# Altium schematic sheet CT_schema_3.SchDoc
size 365 x 192 mm
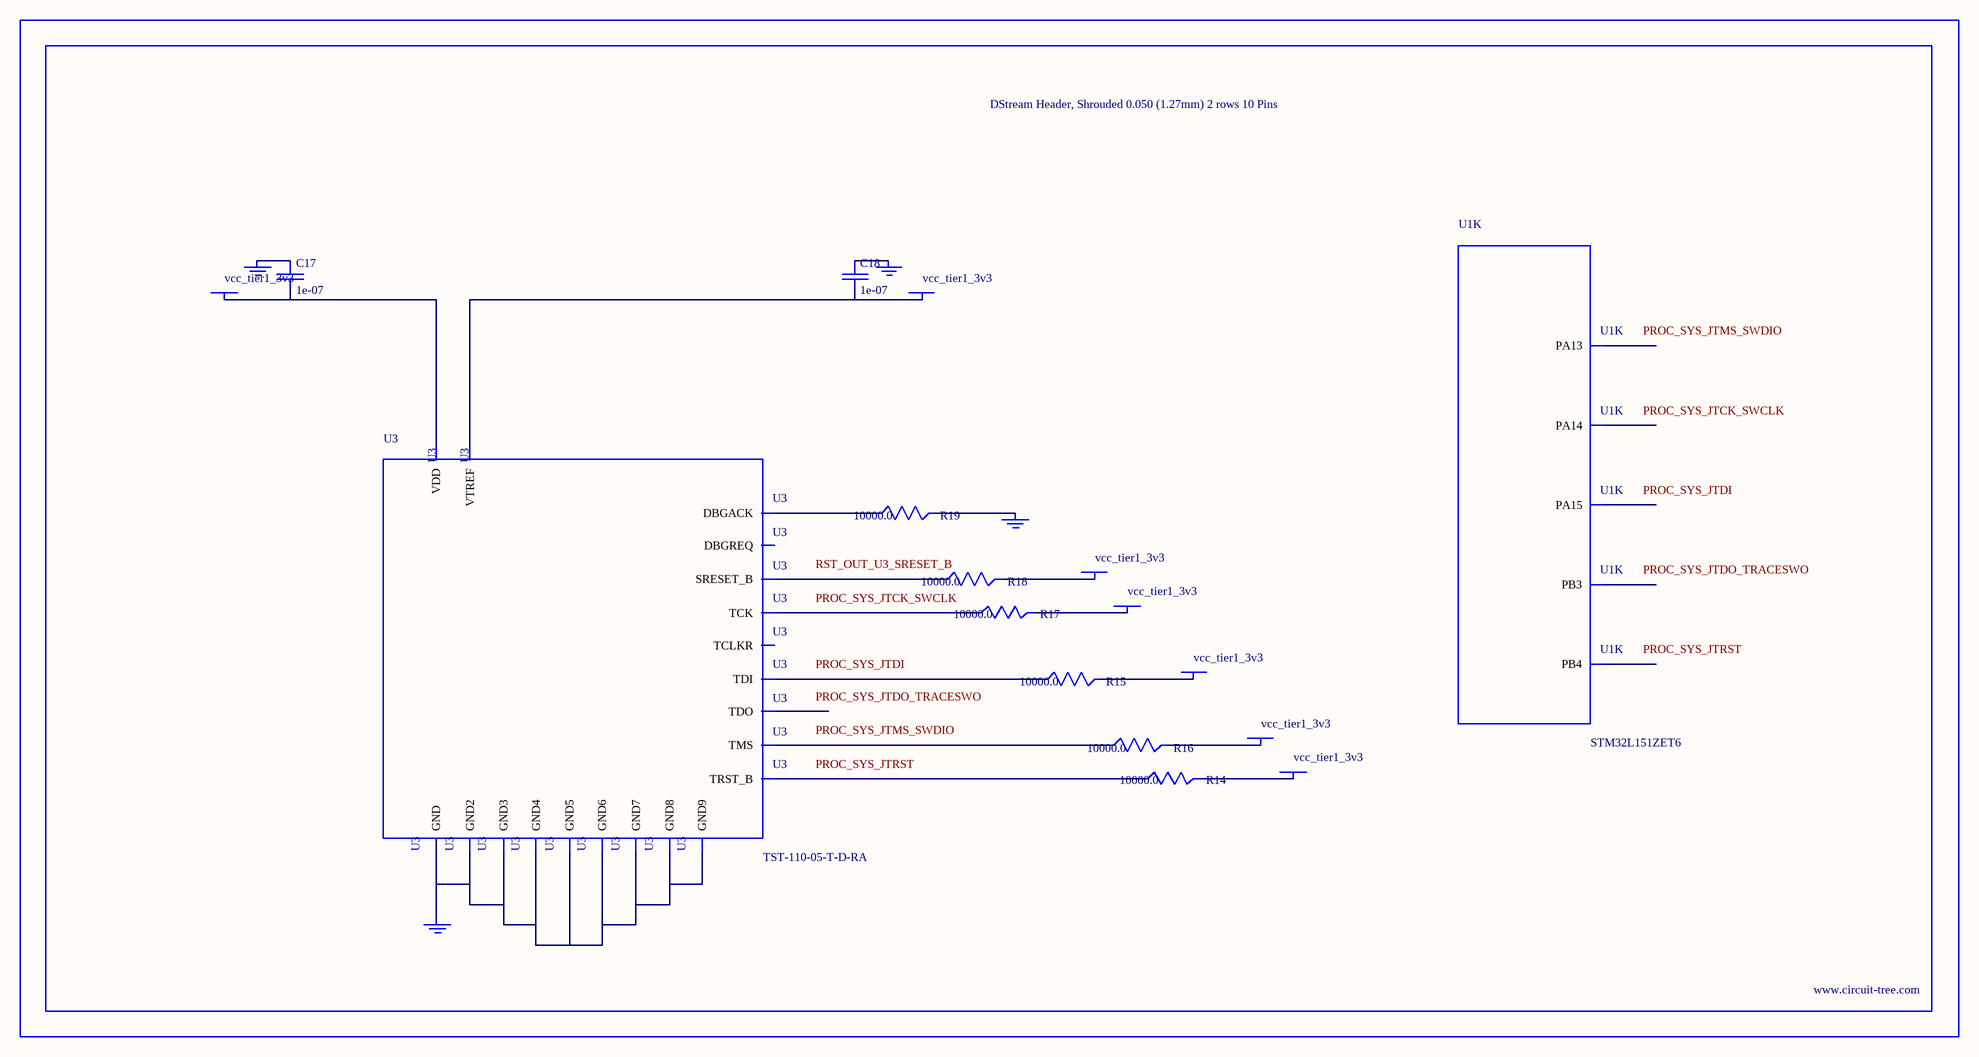
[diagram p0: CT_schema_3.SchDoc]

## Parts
BORDER2  (no value)
C17  1e-07  [C0402]
C18  1e-07  [C0402]
GND_INSTANCE_2_0  (no value)
GND_INSTANCE_2_1  (no value)
GND_INSTANCE_2_2  (no value)
GND_INSTANCE_2_3  (no value)
POWER_INSTANCE_2_0  vcc_tier1_3v3
POWER_INSTANCE_2_1  vcc_tier1_3v3
POWER_INSTANCE_2_2  vcc_tier1_3v3
POWER_INSTANCE_2_3  vcc_tier1_3v3
POWER_INSTANCE_2_4  vcc_tier1_3v3
POWER_INSTANCE_2_5  vcc_tier1_3v3
POWER_INSTANCE_2_6  vcc_tier1_3v3
R14  10000.0  [R0603]
R15  10000.0  [R0603]
R16  10000.0  [R0603]
R17  10000.0  [R0603]
R18  10000.0  [R0603]
R19  10000.0  [R0603]
U1  STM32L151ZET6  [LQFP144]  (part K of 14)
U3  TST-110-05-T-D-RA  [TST-110-05-T-D-RA]

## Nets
NetC17_1: C17.1 GND_INSTANCE_2_1.0(GND)
NetC17_2: C17.2 POWER_INSTANCE_2_1.0(PWR) U3.2(VDD)
NetC18_1: C18.1 GND_INSTANCE_2_0.0(GND)
NetC18_2: C18.2 POWER_INSTANCE_2_0.0(PWR) U3.1(VTREF)
NetGND_INSTANCE_2_2_0: GND_INSTANCE_2_2.0(GND) R19.2
NetGND_INSTANCE_2_3_0: GND_INSTANCE_2_3.0(GND) U3.4(GND) U3.6(GND2) U3.8(GND3) U3.10(GND4) U3.12(GND5) U3.14(GND6) U3.16(GND7) U3.18(GND8) U3.20(GND9)
NetPOWER_INSTANCE_2_2_0: POWER_INSTANCE_2_2.0(PWR) R14.2
NetPOWER_INSTANCE_2_3_0: POWER_INSTANCE_2_3.0(PWR) R15.2
NetPOWER_INSTANCE_2_4_0: POWER_INSTANCE_2_4.0(PWR) R16.2
NetPOWER_INSTANCE_2_5_0: POWER_INSTANCE_2_5.0(PWR) R17.2
NetPOWER_INSTANCE_2_6_0: POWER_INSTANCE_2_6.0(PWR) R18.2
NetR14_1: R14.1 U3.3(TRST_B)
NetR15_1: R15.1 U3.5(TDI)
NetR16_1: R16.1 U3.7(TMS)
NetR17_1: R17.1 U3.9(TCK)
NetR18_1: R18.1 U3.15(SRESET_B)
NetR19_1: R19.1 U3.19(DBGACK)

Not connected (* = marked no-connect by the designer): U1 105(PA13) 109(PA14) 110(PA15) 133(PB3) 134(PB4); U3 11(TCLKR) 13(TDO) 17(DBGREQ)

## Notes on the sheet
- Labels drawn without touching a wire or pin: PROC_SYS_JTCK_SWCLK, PROC_SYS_JTDI, PROC_SYS_JTDO_TRACESWO, PROC_SYS_JTMS_SWDIO, PROC_SYS_JTRST, RST_OUT_U3_SRESET_B

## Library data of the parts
BORDER2 = BORDER_PAGE2
C17 C18 = C0402C104K3RACTU
GND_INSTANCE_2_0-GND_INSTANCE_2_3 = GND
POWER_INSTANCE_2_0-POWER_INSTANCE_2_6 = PWR
R14-R19 = RC0603JR-0710KL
